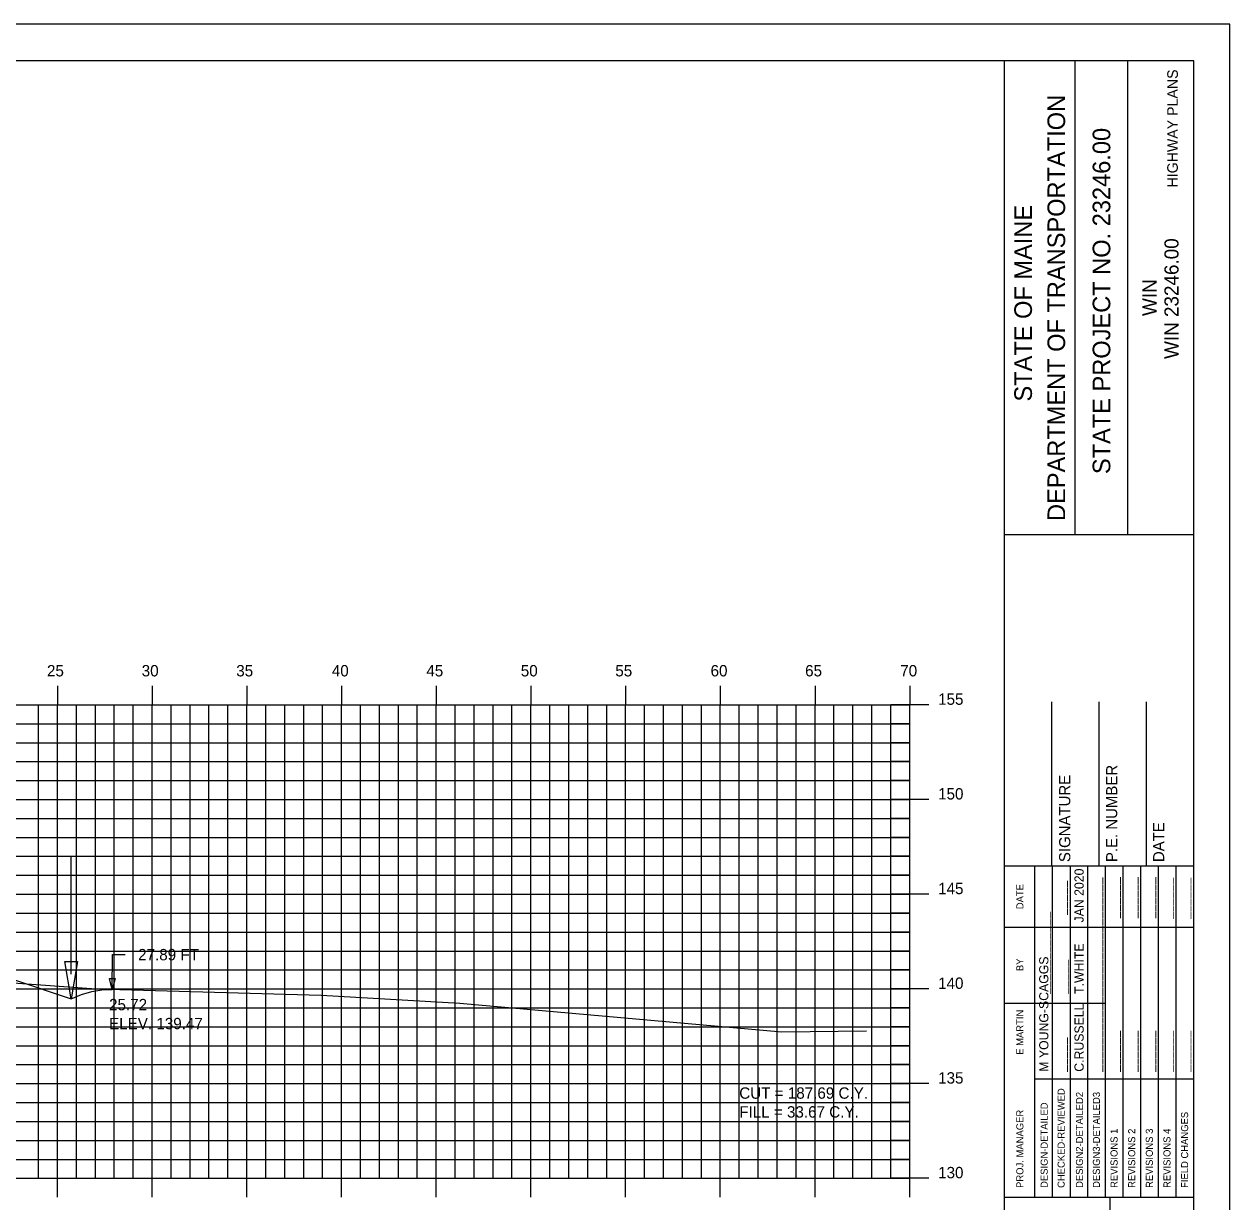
# Model space of a CAD drawing. Extents: x 1144307 to 1144477, y 608981 to 609091.
# Drawn here: x 1144413.3 to 1144477, y 609029.1 to 609091.3 of the extents above; entities that cross this region are included whole.
import ezdxf

# ---------------------------------------------------------------- set-up
doc = ezdxf.new("R2010")
doc.units = 0
for name, color, linetype in [('BORDER', 7, 'Continuous'), ('D_Drainage_Ditch_Line', 7, 'Continuous'), ('D_Roadway_SlopeLines', 7, 'Continuous'), ('D_Text_Standard', 7, 'Continuous'), ('H_V ANNOTATION', 7, 'Continuous'), ('HIGHWAY_TITLE', 7, 'Continuous'), ('MAJOR', 7, 'Continuous'), ('MINOR', 7, 'Continuous'), ('PLOT BOUNDARY', 7, 'Continuous'), ('S_Roadway_Centerline', 7, 'Continuous')]:
    doc.layers.add(name, color=color, linetype=linetype)

msp = doc.modelspace()

# ---------------------------------------------------------------- linework, layer by layer
msp.add_lwpolyline([(1144347.841, 609046.92), (1144349.091, 609046.801), (1144350.341, 609046.537), (1144351.591, 609046.129), (1144352.841, 609045.576), (1144364.381, 609039.806), (1144367.381, 609040.806), (1144375.105, 609043.381), (1144375.106, 609043.381), (1144379.106, 609043.541), (1144390.106, 609043.761), (1144401.106, 609043.541), (1144405.106, 609043.381), (1144412.829, 609040.806), (1144415.829, 609039.806), (1144416.371, 609040.041), (1144416.913, 609040.202), (1144417.454, 609040.291), (1144417.996, 609040.307)])
at = {"layer": 'BORDER'}
for p, q in [((1144465.106, 608984.335), (1144465.106, 609089.335)), ((1144468.835, 609064.332), (1144468.835, 609089.332)), ((1144471.63, 609064.332), (1144471.63, 609089.332)), ((1144465.107, 609064.329), (1144475.106, 609064.329)), ((1144467.606, 609046.838), (1144467.606, 609055.485)), ((1144470.106, 609046.838), (1144470.106, 609055.485)), ((1144472.606, 609046.838), (1144472.606, 609055.485)), ((1144465.106, 609046.838), (1144475.106, 609046.838)), ((1144465.106, 609029.338), (1144475.106, 609029.338)), ((1144470.697, 608994.338), (1144470.697, 609029.338))]:
    msp.add_line(p, q, dxfattribs=at)
msp.add_lwpolyline([(1144315.106, 608984.335), (1144475.106, 608984.335), (1144475.106, 609089.335), (1144315.106, 609089.335)], close=True, dxfattribs=at)
for points in [[(1144466.721, 609043.588), (1144466.721, 609046.838)], [(1144467.653, 609029.341), (1144467.653, 609046.838)], [(1144468.585, 609046.838), (1144468.585, 609029.341)], [(1144469.517, 609029.341), (1144469.517, 609046.838)], [(1144470.449, 609029.341), (1144470.449, 609046.838)], [(1144471.38, 609029.341), (1144471.38, 609046.838)], [(1144472.312, 609029.341), (1144472.312, 609046.838)], [(1144473.244, 609029.341), (1144473.244, 609046.838)], [(1144474.175, 609029.341), (1144474.175, 609046.838)], [(1144466.722, 609029.341), (1144466.722, 609046.132)], [(1144465.106, 609043.588), (1144475.106, 609043.588)], [(1144465.106, 609039.588), (1144466.722, 609039.588)], [(1144466.721, 609039.588), (1144470.448, 609039.588)], [(1144466.721, 609035.588), (1144475.106, 609035.588)]]:
    msp.add_lwpolyline(points, dxfattribs=at)
at = {"layer": 'D_Drainage_Ditch_Line'}
msp.add_line((1144415.829, 609041.119), (1144415.83, 609047.362), dxfattribs=at)
msp.add_lwpolyline([(1144415.501, 609041.775), (1144416.157, 609041.775), (1144415.829, 609039.806)], close=True, dxfattribs=at)
at = {"layer": 'D_Roadway_SlopeLines'}
for points in [[(1144412.829, 609040.806), (1144415.829, 609039.806)], [(1144415.829, 609039.806), (1144416.371, 609040.041), (1144416.913, 609040.202), (1144417.454, 609040.291), (1144417.996, 609040.307)]]:
    msp.add_lwpolyline(points, dxfattribs=at)
at = {"layer": 'D_Text_Standard'}
msp.add_lwpolyline([(1144417.996, 609040.307), (1144418.003, 609042.143), (1144418.683, 609042.143)], dxfattribs=at)
msp.add_lwpolyline([(1144417.996, 609040.307), (1144417.852, 609040.89), (1144418.144, 609040.888)], close=True, dxfattribs=at)
at = {"layer": 'MAJOR'}
for p, q in [((1144415.106, 609056.337), (1144415.106, 609055.335)), ((1144420.106, 609056.337), (1144420.106, 609055.335)), ((1144425.106, 609056.337), (1144425.106, 609055.335)), ((1144430.106, 609056.337), (1144430.106, 609055.335)), ((1144435.106, 609056.337), (1144435.106, 609055.335)), ((1144440.106, 609056.337), (1144440.106, 609055.335)), ((1144445.106, 609056.337), (1144445.106, 609055.335)), ((1144450.106, 609056.337), (1144450.106, 609055.335)), ((1144455.106, 609056.337), (1144455.106, 609055.335)), ((1144460.106, 609056.337), (1144460.106, 609055.335)), ((1144320.106, 609055.335), (1144460.106, 609055.335)), ((1144320.106, 609055.335), (1144460.106, 609055.335)), ((1144415.106, 609030.335), (1144415.106, 609055.335)), ((1144420.106, 609030.335), (1144420.106, 609055.335)), ((1144425.106, 609030.335), (1144425.106, 609055.335)), ((1144430.106, 609030.335), (1144430.106, 609055.335)), ((1144435.106, 609030.335), (1144435.106, 609055.335)), ((1144440.106, 609030.335), (1144440.106, 609055.335)), ((1144445.106, 609030.335), (1144445.106, 609055.335)), ((1144450.106, 609030.335), (1144450.106, 609055.335)), ((1144455.106, 609030.335), (1144455.106, 609055.335)), ((1144461.108, 609055.335), (1144459.104, 609055.335)), ((1144460.106, 609030.335), (1144460.106, 609055.335)), ((1144460.106, 609030.335), (1144460.106, 609055.335)), ((1144320.106, 609050.335), (1144460.106, 609050.335)), ((1144461.108, 609050.335), (1144459.104, 609050.335)), ((1144320.106, 609045.335), (1144460.106, 609045.335)), ((1144461.108, 609045.335), (1144459.104, 609045.335)), ((1144320.106, 609040.335), (1144460.106, 609040.335)), ((1144461.108, 609040.335), (1144459.104, 609040.335)), ((1144320.106, 609035.335), (1144460.106, 609035.335)), ((1144461.108, 609035.335), (1144459.104, 609035.335)), ((1144320.106, 609030.335), (1144460.106, 609030.335)), ((1144320.106, 609030.335), (1144460.106, 609030.335)), ((1144415.106, 609029.333), (1144415.106, 609030.335)), ((1144420.106, 609029.333), (1144420.106, 609030.335)), ((1144425.106, 609029.333), (1144425.106, 609030.335)), ((1144430.106, 609029.333), (1144430.106, 609030.335)), ((1144435.106, 609029.333), (1144435.106, 609030.335)), ((1144440.106, 609029.333), (1144440.106, 609030.335)), ((1144445.106, 609029.333), (1144445.106, 609030.335)), ((1144450.106, 609029.333), (1144450.106, 609030.335)), ((1144455.106, 609029.333), (1144455.106, 609030.335)), ((1144461.108, 609030.335), (1144459.104, 609030.335)), ((1144460.106, 609029.333), (1144460.106, 609030.335))]:
    msp.add_line(p, q, dxfattribs=at)
at = {"layer": 'MINOR'}
for p, q in [((1144414.106, 609030.335), (1144414.106, 609055.335)), ((1144416.106, 609030.335), (1144416.106, 609055.335)), ((1144417.106, 609030.335), (1144417.106, 609055.335)), ((1144418.106, 609030.335), (1144418.106, 609055.335)), ((1144419.106, 609030.335), (1144419.106, 609055.335)), ((1144421.106, 609030.335), (1144421.106, 609055.335)), ((1144422.106, 609030.335), (1144422.106, 609055.335)), ((1144423.106, 609030.335), (1144423.106, 609055.335)), ((1144424.106, 609030.335), (1144424.106, 609055.335)), ((1144426.106, 609030.335), (1144426.106, 609055.335)), ((1144427.106, 609030.335), (1144427.106, 609055.335)), ((1144428.106, 609030.335), (1144428.106, 609055.335)), ((1144429.106, 609030.335), (1144429.106, 609055.335)), ((1144431.106, 609030.335), (1144431.106, 609055.335)), ((1144432.106, 609030.335), (1144432.106, 609055.335)), ((1144433.106, 609030.335), (1144433.106, 609055.335)), ((1144434.106, 609030.335), (1144434.106, 609055.335)), ((1144436.106, 609030.335), (1144436.106, 609055.335)), ((1144437.106, 609030.335), (1144437.106, 609055.335)), ((1144438.106, 609030.335), (1144438.106, 609055.335)), ((1144439.106, 609030.335), (1144439.106, 609055.335)), ((1144441.106, 609030.335), (1144441.106, 609055.335)), ((1144442.106, 609030.335), (1144442.106, 609055.335)), ((1144443.106, 609030.335), (1144443.106, 609055.335)), ((1144444.106, 609030.335), (1144444.106, 609055.335)), ((1144446.106, 609030.335), (1144446.106, 609055.335)), ((1144447.106, 609030.335), (1144447.106, 609055.335)), ((1144448.106, 609030.335), (1144448.106, 609055.335)), ((1144449.106, 609030.335), (1144449.106, 609055.335)), ((1144451.106, 609030.335), (1144451.106, 609055.335)), ((1144452.106, 609030.335), (1144452.106, 609055.335)), ((1144453.106, 609030.335), (1144453.106, 609055.335)), ((1144454.106, 609030.335), (1144454.106, 609055.335)), ((1144456.106, 609030.335), (1144456.106, 609055.335)), ((1144457.106, 609030.335), (1144457.106, 609055.335)), ((1144458.106, 609030.335), (1144458.106, 609055.335)), ((1144459.106, 609030.335), (1144459.106, 609055.335)), ((1144320.106, 609054.335), (1144460.106, 609054.335)), ((1144460.106, 609054.335), (1144459.104, 609054.335)), ((1144320.106, 609053.335), (1144460.106, 609053.335)), ((1144460.106, 609053.335), (1144459.104, 609053.335)), ((1144320.106, 609052.335), (1144460.106, 609052.335)), ((1144460.106, 609052.335), (1144459.104, 609052.335)), ((1144320.106, 609051.335), (1144460.106, 609051.335)), ((1144460.106, 609051.335), (1144459.104, 609051.335)), ((1144320.106, 609049.335), (1144460.106, 609049.335)), ((1144460.106, 609049.335), (1144459.104, 609049.335)), ((1144320.106, 609048.335), (1144460.106, 609048.335)), ((1144460.106, 609048.335), (1144459.104, 609048.335)), ((1144320.106, 609047.335), (1144460.106, 609047.335)), ((1144460.106, 609047.335), (1144459.104, 609047.335)), ((1144320.106, 609046.335), (1144460.106, 609046.335)), ((1144460.106, 609046.335), (1144459.104, 609046.335)), ((1144320.106, 609044.335), (1144460.106, 609044.335)), ((1144460.106, 609044.335), (1144459.104, 609044.335)), ((1144320.106, 609043.335), (1144460.106, 609043.335)), ((1144460.106, 609043.335), (1144459.104, 609043.335)), ((1144320.106, 609042.335), (1144460.106, 609042.335)), ((1144460.106, 609042.335), (1144459.104, 609042.335)), ((1144320.106, 609041.335), (1144460.106, 609041.335)), ((1144460.106, 609041.335), (1144459.104, 609041.335)), ((1144320.106, 609039.335), (1144460.106, 609039.335)), ((1144460.106, 609039.335), (1144459.104, 609039.335)), ((1144320.106, 609038.335), (1144460.106, 609038.335)), ((1144460.106, 609038.335), (1144459.104, 609038.335)), ((1144320.106, 609037.335), (1144460.106, 609037.335)), ((1144460.106, 609037.335), (1144459.104, 609037.335)), ((1144320.106, 609036.335), (1144460.106, 609036.335)), ((1144460.106, 609036.335), (1144459.104, 609036.335)), ((1144320.106, 609034.335), (1144460.106, 609034.335)), ((1144460.106, 609034.335), (1144459.104, 609034.335)), ((1144320.106, 609033.335), (1144460.106, 609033.335)), ((1144460.106, 609033.335), (1144459.104, 609033.335)), ((1144320.106, 609032.335), (1144460.106, 609032.335)), ((1144460.106, 609032.335), (1144459.104, 609032.335)), ((1144320.106, 609031.335), (1144460.106, 609031.335)), ((1144460.106, 609031.335), (1144459.104, 609031.335))]:
    msp.add_line(p, q, dxfattribs=at)
at = {"layer": 'PLOT BOUNDARY'}
msp.add_lwpolyline([(1144307.013, 608981.276), (1144477.013, 608981.276), (1144477.013, 609091.276), (1144307.013, 609091.276)], close=True, dxfattribs=at)
at = {"layer": 'S_Roadway_Centerline'}
msp.add_lwpolyline([(1144331.776, 609047.722), (1144338.331, 609047.454), (1144341.656, 609047.153), (1144360.447, 609046.446), (1144368.741, 609042.792), (1144370.997, 609041.915), (1144371.562, 609042.052), (1144374.332, 609042.69), (1144377.15, 609042.85), (1144377.609, 609042.884), (1144379.365, 609042.911), (1144387.536, 609043.076), (1144389.604, 609042.982), (1144399.223, 609042.594), (1144399.771, 609042.526), (1144402.744, 609042.235), (1144403.907, 609041.822), (1144406.963, 609041.271), (1144409.332, 609040.909), (1144417.14, 609040.331), (1144429.035, 609039.996), (1144436.353, 609039.584), (1144453.352, 609038.069), (1144457.816, 609038.12)], dxfattribs=at)

# ---------------------------------------------------------------- texts
at = {"layer": 'BORDER'}
for s, height, p in [('DEPARTMENT OF TRANSPORTATION', 0.93176, (1144468.313, 609065.041)), ('STATE PROJECT NO. 23246.00', 0.93176, (1144470.698, 609067.517)), ('STATE OF MAINE', 0.93176, (1144466.561, 609071.347)), ('WIN 23246.00', 0.74527, (1144474.302, 609073.596)), ('WIN', 0.7453, (1144473.143, 609075.865)), ('P.E. NUMBER', 0.59055, (1144471.067, 609047.03)), ('SIGNATURE', 0.5906, (1144468.586, 609047.03)), ('DATE', 0.5906, (1144473.547, 609047.03)), ('JAN 2020', 0.4845, (1144469.292, 609043.843)), ('______', 0.4845, (1144470.187, 609044.063)), ('______', 0.4845, (1144471.118, 609044.065)), ('______', 0.4845, (1144472.05, 609044.067)), ('______', 0.4845, (1144472.982, 609044.067)), ('______', 0.4845, (1144473.913, 609044.036)), ('______', 0.4845, (1144474.845, 609044.036)), ('DATE', 0.3714, (1144466.11, 609044.544)), ('_____', 0.4845, (1144468.323, 609044.243)), ('____________', 0.48455, (1144467.429, 609040.073)), ('____________', 0.48455, (1144470.187, 609040.073)), ('T.WHITE', 0.4845, (1144469.292, 609040.073)), ('BY', 0.3714, (1144466.11, 609041.273)), ('M YOUNG-SCAGGS', 0.48455, (1144467.429, 609035.961)), ('_____', 0.4845, (1144468.361, 609040.073)), ('____________', 0.48455, (1144470.187, 609035.961)), ('C.RUSSELL', 0.4845, (1144469.292, 609035.961)), ('E MARTIN', 0.3727, (1144466.11, 609036.855)), ('______', 0.4845, (1144471.118, 609035.961)), ('______', 0.4845, (1144472.05, 609035.961)), ('______', 0.4845, (1144472.982, 609035.961)), ('______', 0.4845, (1144473.913, 609035.961)), ('______', 0.4845, (1144474.845, 609035.961)), ('_____', 0.4845, (1144468.323, 609035.961)), ('CHECKED-REVIEWED', 0.37275, (1144468.287, 609029.826)), ('DESIGN2-DETAILED2', 0.37275, (1144469.256, 609029.826)), ('DESIGN3-DETAILED3', 0.37275, (1144470.15, 609029.826)), ('DESIGN-DETAILED', 0.37275, (1144467.393, 609029.826)), ('PROJ. MANAGER', 0.37275, (1144466.11, 609029.826)), ('FIELD CHANGES', 0.37275, (1144474.809, 609029.826)), ('REVISIONS 1', 0.37275, (1144471.082, 609029.826)), ('REVISIONS 2', 0.37275, (1144472.014, 609029.826)), ('REVISIONS 3', 0.37275, (1144472.945, 609029.826)), ('REVISIONS 4', 0.37275, (1144473.877, 609029.826))]:
    msp.add_text(s, height=height, rotation=90, dxfattribs=at).set_placement(p)
at = {"layer": 'D_Text_Standard'}
for s, p in [('27.89 FT', (1144419.363, 609041.843)), ('25.72', (1144417.829, 609039.206)), ('ELEV. 139.47', (1144417.829, 609038.204)), ('CUT = 187.69 C.Y.', (1144451.106, 609034.535)), ('FILL = 33.67 C.Y.', (1144451.106, 609033.539))]:
    msp.add_text(s, height=0.6, dxfattribs=at).set_placement(p)
at = {"layer": 'H_V ANNOTATION'}
for s, p in [('25', (1144414.552, 609056.835)), ('30', (1144419.554, 609056.835)), ('35', (1144424.546, 609056.835)), ('40', (1144429.592, 609056.835)), ('45', (1144434.584, 609056.835)), ('50', (1144439.57, 609056.835)), ('55', (1144444.562, 609056.835)), ('60', (1144449.592, 609056.835)), ('65', (1144454.584, 609056.835)), ('70', (1144459.608, 609056.835)), ('155', (1144461.606, 609055.335)), ('150', (1144461.606, 609050.335)), ('145', (1144461.606, 609045.335)), ('140', (1144461.606, 609040.335)), ('135', (1144461.606, 609035.335)), ('130', (1144461.606, 609030.335))]:
    msp.add_text(s, height=0.6, dxfattribs=at).set_placement(p)
at = {"layer": 'HIGHWAY_TITLE'}
msp.add_text('HIGHWAY PLANS', height=0.55901, rotation=90, dxfattribs=at).set_placement((1144474.264, 609082.65))

doc.saveas('drawing.dxf')
